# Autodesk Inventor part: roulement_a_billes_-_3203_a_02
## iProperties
Shininess: 64.0
Length Units: 11269
Angle Units: 11279
Time Units: 11290
Mass Units: 11283
Length Display Precision: 3
Angle Display Precision: 2
Compacted: True
Part Number: roulement_a_billes_-_3203_a_02
Document SubType Name: Modeling
Created: 2005-02
Material: Par défaut
Designer: LEGERET Philippe
Density: 0.0
Volumn: 0.0
Area: 0.0
PropertySet Name: Model Information
Control State: 0
Master: False
Checked Out: False
Author: LEGERET Philippe
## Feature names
1. Base1
